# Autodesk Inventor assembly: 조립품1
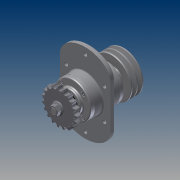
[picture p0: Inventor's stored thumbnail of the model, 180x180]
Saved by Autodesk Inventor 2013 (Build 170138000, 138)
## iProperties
Created: 2015-02
Part Number: 조립품1
Document SubType Name: Assembly
Designer: cad8
Author: cad8
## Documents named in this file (12)
- C:\Documents and Settings\cad8\바탕 화면\450208V1016\조립품1.iam
- C:\Documents and Settings\cad8\바탕 화면\450208V1016\2-커버.ipt
- C:\Documents and Settings\cad8\바탕 화면\450208V1016\3-축.ipt
- C:\Documents and Settings\cad8\바탕 화면\450208V1016\4-V벨트풀리.ipt
- C:\Documents and Settings\cad8\바탕 화면\450208V1016\5-체인 스프로킷.ipt
- C:\Documents and Settings\cad8\바탕 화면\450208V1016\6-베어링 6206.ipt
- C:\Documents and Settings\cad8\바탕 화면\450208V1016\7-부시.ipt
- C:\Documents and Settings\cad8\바탕 화면\450208V1016\8-오일실 30x42.ipt
- C:\Documents and Settings\cad8\바탕 화면\450208V1016\9-M16-너트.ipt
- C:\Documents and Settings\cad8\바탕 화면\450208V1016\10-M6.ipt
- C:\Documents and Settings\cad8\바탕 화면\450208V1016\11-키 6x6.ipt
- C:\Documents and Settings\cad8\바탕 화면\450208V1016\본체.ipt
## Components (22 placed, 10 different names)
1. 2-커버:1
2. 3-축:1
3. 4-V벨트풀리:1
4. 5-체인 스프로킷:1
5. 6-베어링 6206:1
6. 7-부시:1
7. 8-8-오일실 30x42:1
8. 9-M16 너트:1
9. 11-키 6x6:1
10. 6-베어링 6206:2
11. 2-커버:2
12. 8-8-오일실 30x42:2
13. 11-키 6x6:2
14. 9-M16 너트:2
15. 10-M6:2
16. 10-M6:3
17. 10-M6:4
18. 10-M6:5
19. 10-M6:1
20. 10-M6:6
21. 10-M6:7
22. 10-M6:8
